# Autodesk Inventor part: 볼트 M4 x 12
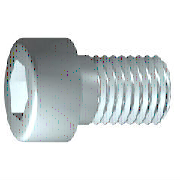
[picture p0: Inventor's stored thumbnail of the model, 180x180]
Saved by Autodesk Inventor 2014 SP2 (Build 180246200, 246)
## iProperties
IsCustomPart: 0
Created: 2012-02
Part Number: 볼트 M4 x 12
Material: 강철, 연강
Description: 6각 소켓 머리 캡 나사
Document SubType Name: Modeling
Standard: ISO 4762
Designer: mduedu
Standard Revision: Fourth edition 2004-03-01
Standards Organization: ISO
Language: ko-KR
Size Designation: M4 x 12
Categories: <MemberInstance><Categories><Category DisplayName="조임쇠" InternalName="e4da775c-781d-43d5-af7c-5136215cf5a6" Mnemonic="FSTN"><Category DisplayName="볼트" InternalN
Density: 7.75 g/cm^3
Appearance: 강철
Author: mduedu
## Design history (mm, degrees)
sketch "스케치1"
  geometry: L1 (-1, 0)-(12, 0); L2 (12, 0)-(12, 2); L3 (12, 2)-(1.75, 2); L4 (1.75, 2)-(1.32, 2); L5 (1.32, 2)-(0, 2); L6 (0, 2)-(0, 3.5); L7 (0, 3.5)-(-4, 3.5); L8 (-4, 3.5)-(-4, 1.732); L9 (-4, 1.732)-(-2, 1.732); L10 (-2, 1.732)-(-1, 0); L11 (-7.2, 0)-(15.2, 0) reference; L12 (0, -0.7)-(0, 4.2) reference; L13 (1.75, 2)-(0, 2)
  constraints: 22 end point, 6 parallel, 2 collinear, 2 perpendicular, 1 horizontal, 1 point on line
  dimensions: "d1" = 10.25 distance from line of L3.end L2 (= GEL); "d2" = 0.42952 distance of L4.end L3.end (computed from GAL); "d3" = 4 distance between parallel lines of L8 L6 (= KOH); "d4" = 2 distance of L8.end L9.end (= INTI); "d5" = 60 deg angle of L10 L1; "d6" = 4 diameter of L3 L1 (= GD); "d7" = 4 diameter of L5 L1 (= BDM); "d8" = 3.4641 diameter of L9 L1 (= 1.1547 x SW); "d9" = 7 diameter of L7 L1 (= KOD); "d26" = 12 distance between parallel lines of L12 L2 (= NLG)
revolve "본체" sketch "스케치1" stored, may be unused: angle "d10" = 90 deg
sketch "스케치2"
  geometry: L1 (0, -4.9)-(0, 4.9) reference; L2 (-4.9, 0)-(4.9, 0) reference; L3 (1.732, 0)-(0.866, -1.5); L4 (0.866, -1.5)-(-0.866, -1.5); L5 (-0.866, -1.5)-(-1.732, 0); L6 (-1.732, 0)-(-0.866, 1.5); L7 (-0.866, 1.5)-(0.866, 1.5); L8 (0.866, 1.5)-(1.732, 0); 2 further points
  constraints: 12 end point, 1 coincident, 1 horizontal alignment, 1 point on line, 12 other
extrude "슬롯" join sketch "스케치2" stored distance "d11" = 10; taper "d12" = 0 deg
workplane "Work Plane1"
fillet "Fillet2" dims "d30" = 0.1 (= R)
body "Solid1"
fillet "모깎기1" dims "d17" = 0.4 (= RR)
feature "스레드" dims "d13" = 10.25 (= GEL), "d14" = 0
chamfer "모따기1" distance "d15" = 0.42941 (= -0.5 x SPD + 0.5 x GD); stored, may be unused: second distance "d16" = 0.42941 (= GUL), angle "d27" = 45 deg
other parameters: "GD" = 4 [user parameter; used in 2 equation terms], "NLG" = 12 [user parameter; used in 1 equation term], "GEL" = 10.25 [user parameter; used in 2 equation terms], "KOD" = 7 [user parameter; used in 1 equation term], "KOH" = 4 [user parameter; used in 1 equation term], "INTI" = 2 [user parameter; used in 1 equation term], "GAL" = 0.42941 (= 0.61345 x PTC) [user parameter; used in 1 equation term], "GUL" = 0.42941 (= 0.61345 x PTC) [user parameter; used in 1 equation term], "BDM" = 4 (= NND) [user parameter; used in 1 equation term], "SW" = 3 [user parameter; used in 2 equation terms], "RR" = 0.4 [user parameter; used in 1 equation term], "SPD" = 3.14117 (= NND - 1.2269 x PTC) [user parameter; used in 1 equation term], "d19" = 0, "d28" = 0, "d29" = 0, "R" = 0.1 [user parameter; used in 1 equation term], "TOA" = 30 deg [user parameter], "GD1" = 3.14117 (= THREADDIA - 1.2269 x PTC) [user parameter], "THREADDIA" = 4 [user parameter; used in 1 equation term], "FAWI" = 45 deg [user parameter], "TPU" = 14.28571 (computed from PTC) [user parameter], "PTC" = 0.7 [user parameter; used in 5 equation terms], "NND" = 4 [user parameter; used in 2 equation terms], "E0" = 3.465 (= 1.155 x SW) [user parameter]
